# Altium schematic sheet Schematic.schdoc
size 784 x 211 mm
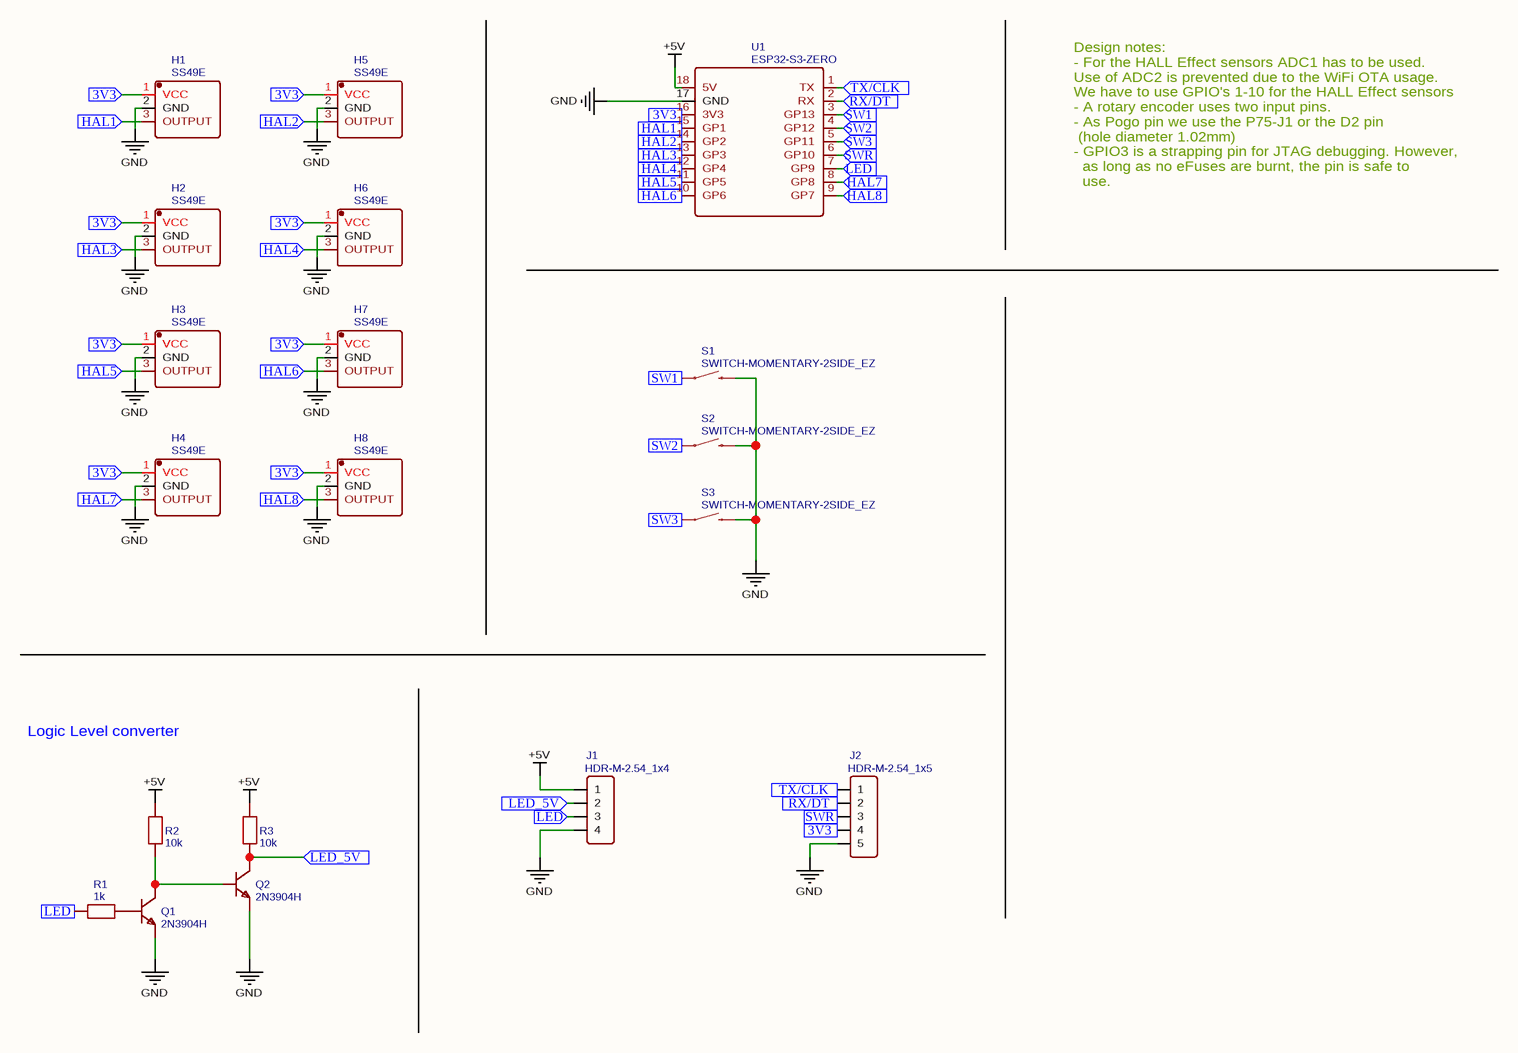
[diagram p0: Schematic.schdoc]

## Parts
H1  SS49E  [SS49EHALL_TO-92FLAT]
H2  SS49E  [SS49EHALL_TO-92FLAT]
H3  SS49E  [SS49EHALL_TO-92FLAT]
H4  SS49E  [SS49EHALL_TO-92FLAT]
H5  SS49E  [SS49EHALL_TO-92FLAT]
H6  SS49E  [SS49EHALL_TO-92FLAT]
H7  SS49E  [SS49EHALL_TO-92FLAT]
H8  SS49E  [SS49EHALL_TO-92FLAT]
J1  HDR-M-2.54_1x4  [HDR-M-2.54_1X4]
J2  HDR-M-2.54_1x5  [HDR-M-2.54_1X5]
Q1  2N3904H  [TO-92-3_L4.8-W3.7-P1.27-L-1]
Q2  2N3904H  [TO-92-3_L4.8-W3.7-P1.27-L-1]
R1  1k  [R_AXIAL-0.3]
R2  10k  [R_AXIAL-0.3]
R3  10k  [R_AXIAL-0.3]
S1  SWITCH-MOMENTARY-2SIDE_EZ  [TACTILE-PTH-SIDEEZ]
S2  SWITCH-MOMENTARY-2SIDE_EZ  [TACTILE-PTH-SIDEEZ]
S3  SWITCH-MOMENTARY-2SIDE_EZ  [TACTILE-PTH-SIDEEZ]
U1  ESP32-S3-ZERO  [ESP_ZERO]

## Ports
3V3 (in), HAL1 (in), HAL2 (in), HAL3 (in), HAL4 (in), HAL5 (in), HAL6 (in), HAL7 (in), HAL8 (in), LED (in), LED_5V (in), RX/DT (in), SW1 (in), SW2 (in), SW3 (in), SWR (in), TX/CLK (in)

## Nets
+5V: J1.1 R2.2 R3.2 U1.18(5V)
GND: H1.2(GND) H2.2(GND) H3.2(GND) H4.2(GND) H5.2(GND) H6.2(GND) H7.2(GND) H8.2(GND) J1.4 J2.5 Q1.1(E) Q2.1(E) S1.2 S2.2 S3.2 U1.17(GND)
3V3: H1.1(VCC) H2.1(VCC) H3.1(VCC) H4.1(VCC) H5.1(VCC) H6.1(VCC) H7.1(VCC) H8.1(VCC) J2.4 U1.16(3V3) ; port 3V3
HAL1: H1.3(OUTPUT) U1.15(GP1) ; port HAL1
HAL2: H5.3(OUTPUT) U1.14(GP2) ; port HAL2
HAL3: H2.3(OUTPUT) U1.13(GP3) ; port HAL3
HAL4: H6.3(OUTPUT) U1.12(GP4) ; port HAL4
HAL5: H3.3(OUTPUT) U1.11(GP5) ; port HAL5
HAL6: H7.3(OUTPUT) U1.10(GP6) ; port HAL6
HAL7: H4.3(OUTPUT) U1.8(GP8) ; port HAL7
HAL8: H8.3(OUTPUT) U1.9(GP7) ; port HAL8
LED: J1.3 R1.1 U1.7(GP9) ; port LED
LED_5V: J1.2 Q2.3(C) R3.1 ; port LED_5V
RX/DT: J2.2 U1.2(RX) ; port RX/DT
SW1: S1.1 U1.3(GP13) ; port SW1
SW2: S2.1 U1.4(GP12) ; port SW2
SW3: S3.1 U1.5(GP11) ; port SW3
SWR: J2.3 U1.6(GP10) ; port SWR
TX/CLK: J2.1 U1.1(TX) ; port TX/CLK
NetQ1_2: Q1.2(B) R1.2
NetQ1_3: Q1.3(C) Q2.2(B) R2.1

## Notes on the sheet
- Design notes:
  - For the HALL Effect sensors ADC1 has to be used.
  Use of ADC2 is prevented due to the WiFi OTA usage.
  We have to use GPIO's 1-10 for the HALL Effect sensors
  - A rotary encoder uses two input pins.
  - As Pogo pin we use the P75-J1 or the D2 pin
  (hole diameter 1.02mm)
  - GPIO3 is a strapping pin for JTAG debugging. However,
  as long as no eFuses are burnt, the pin is safe to
  use.
- Logic Level converter

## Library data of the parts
H1-H8 = SS49E: Contributor: Andrew Melnikov
J1 = HDR-M-2.54_1x4: Contributor: LCEDA_Lib
J2 = HDR-M-2.54_1x5: Contributor: LCEDA_Lib
Q1 Q2 = 2N3904H: Manufacturer: onsemi(安森美); Contributor: lcsc
R1 = 1k: nameAlias: Value(Ω); Contributor: LCEDA_Lib
R2 R3 = 10k: nameAlias: Value(Ω); Contributor: LCEDA_Lib
S1-S3 = SWITCH-MOMENTARY-2SIDE_EZ: Contributor: Rik Roy
U1 = ESP32-S3-ZERO: Manufacturer: Waveshare; Contributor: lcsc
